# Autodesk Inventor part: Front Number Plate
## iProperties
Shininess: 21.0
Angle Display Precision: 2
Document Length Units: 11269
Document Angle Units: 11279
Document Time Units: 11290
Document Mass Units: 11283
Document Length Units Precision: 3
Document Angle Units Precision: 2
Compacted: True
Created: 2001-08
Part Number: Front Number Plate
Document SubType Name: Modeling
Designer: Martin Budgell
Density: 0.0
Volumn: 0.0
Area: 0.0
PropertySet Name: Model Information
Control State: 0
Master: False
Checked Out: False
Author: Martin Budgell
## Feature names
1. Extrusion1
2. Fillet1
3. Extrusion2
4. Fillet2
5. Extrusion3
6. Extrusion5
